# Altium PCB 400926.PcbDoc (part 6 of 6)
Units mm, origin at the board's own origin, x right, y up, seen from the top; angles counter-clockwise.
Board outline 148.5 x 63.5 mm, 4 copper layers (Top Layer, Mid-Layer 1, Mid-Layer 2, Bottom Layer), stack 1.514 mm thick; 311 components, 281 nets, 1495 pads, 2232 vias.
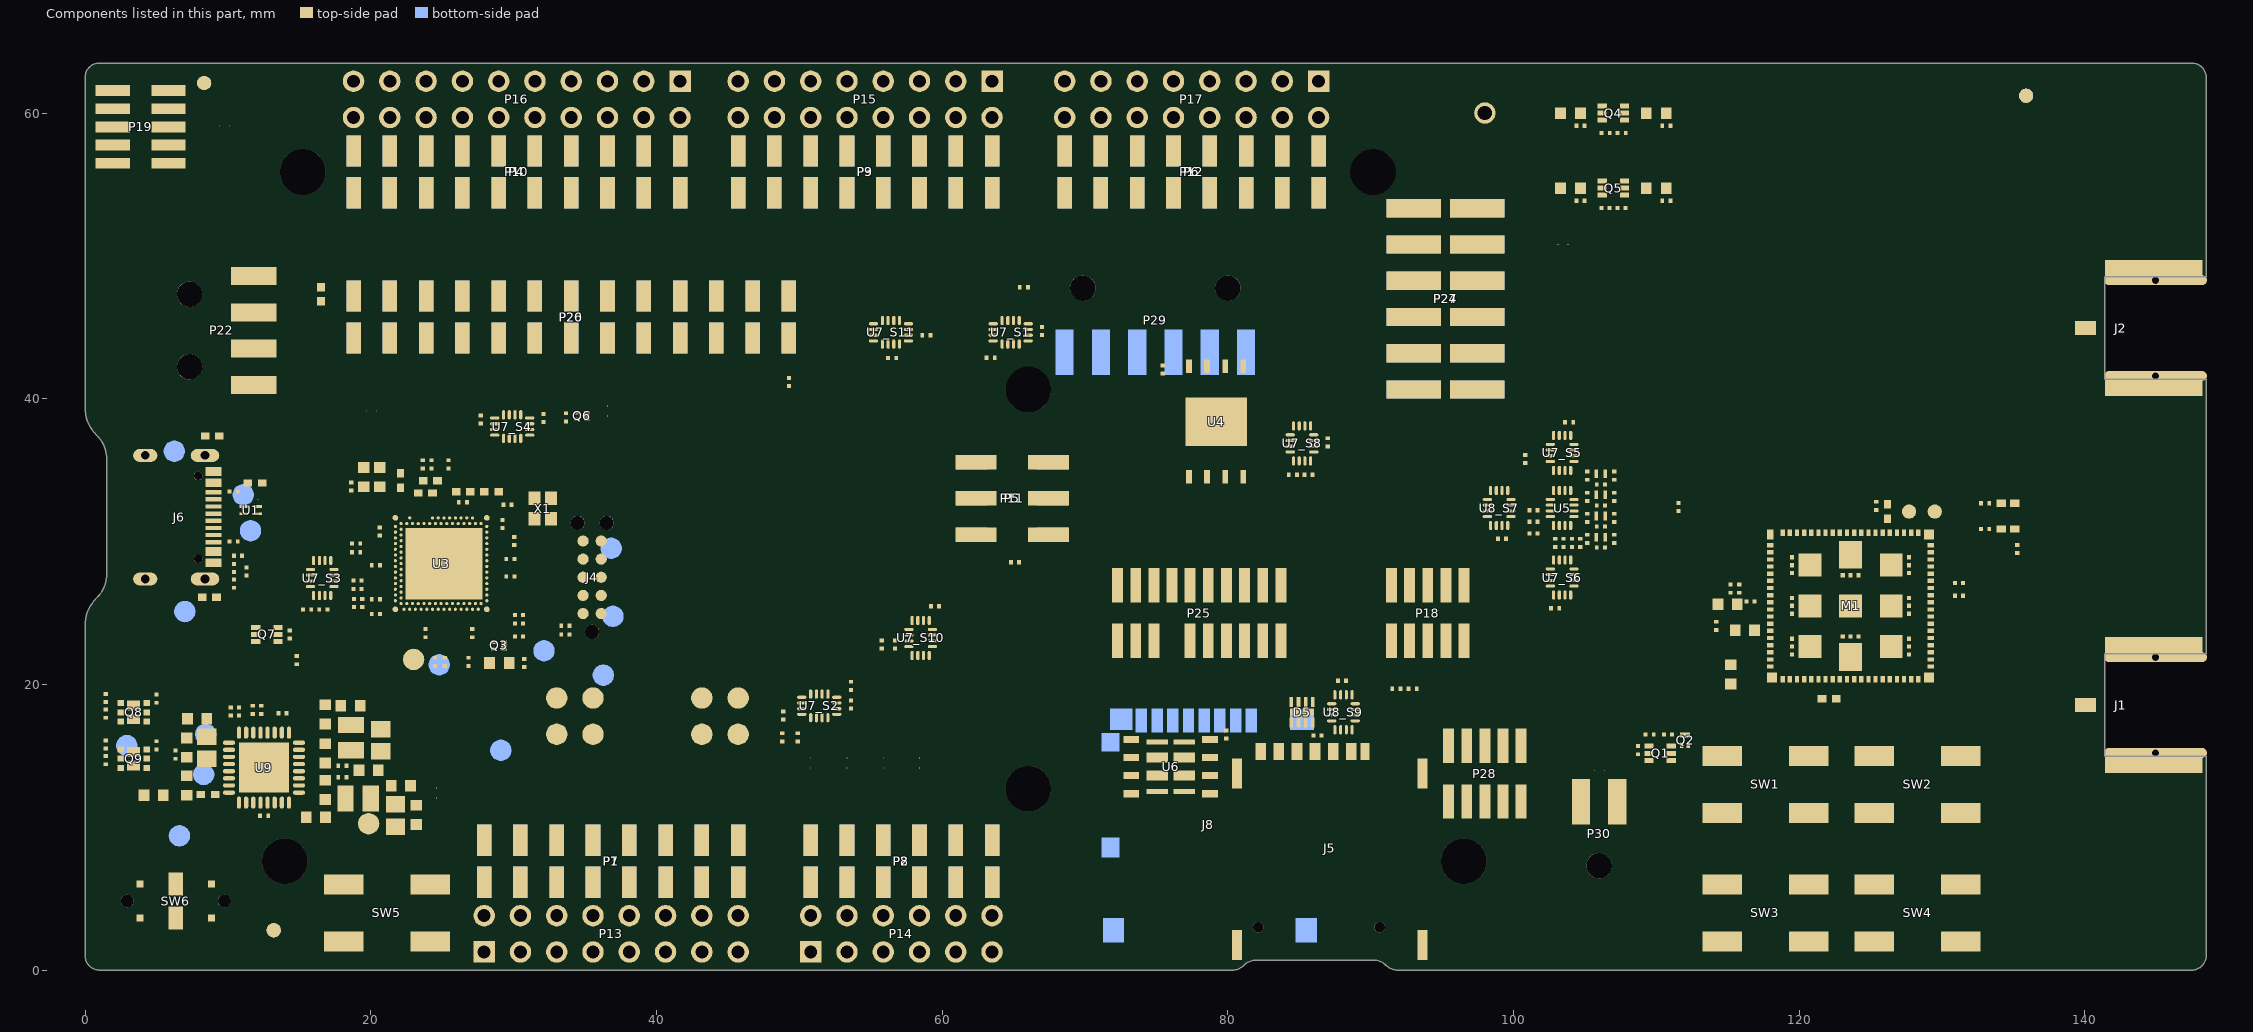
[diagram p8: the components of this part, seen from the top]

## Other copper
Top Layer:
  region net VIN:5V: 39.626,46.224 38.606,46.224 38.606,45.224 39.626,45.224
  region net VDD_nRF: 42.166,46.224 41.146,46.224 41.146,45.224 42.166,45.224
  region net LTE_RF1: 125.7,20.149 125.527,19.976 ccw(c125.954,19.549) 125.35,19.549 126.35,19.549 ccw(c125.746,19.549) 126.173,19.976 126,20.149 126,20.599 125.7,20.599
  region net GPS_RF1: 129.45,21.099 129.623,20.926 ccw(c130.05,21.352) 130.05,20.749 130.05,21.749 ccw(c130.05,21.145) 129.623,21.572 129.45,21.399 129,21.399 129,21.099
  region net VDD_1V8: 14.7,12.574 14.7,11.249 ccw(c16.45,11.249) 16.45,9.499 20.025,9.499 ccw(c20.025,10.074) 20.6,10.074 20.6,12.906 19.432,12.906 19.432,11.031 cw(c19.1,11.031) 19.1,10.699 ccw(c19.1,10.499) 18.9,10.499 18.9,10.299 cw(c18.725,10.299) 18.725,10.124 16.3,10.124 cw(c16.3,10.599) 15.825,10.599 15.825,11.604 15.25,12.084 15.25,12.574
  region net NetC70_2: 21.506,10.571 21.506,10.573 23.622,10.573 ccw(c23.622,11.07) 24.119,11.07 cw(c24.147,11.07) 24.147,11.098 25.011,11.098 cw(c25.011,11.022) 25.087,11.022 25.087,9.686 cw(c24.9,9.686) 24.9,9.499 21.074,9.499 cw(c21.074,9.521) 21.052,9.521 21.052,10.571
  region net VDD_1V8: 19.432,12.906 20.662,12.906 ccw(c20.662,13.296) 21.052,13.296 21.802,13.296 21.802,12.496 ccw(c22.177,12.496) 22.177,12.121 22.402,12.121 22.402,11.071 19.432,11.071
  region net NetC59_2: 16.427,18.958 cw(c16.465,18.958) 16.465,18.996 18.402,18.996 18.402,18.196 ccw(c18.874,18.196) 18.874,17.724 21.05,17.724 cw(c21.05,17.399) 21.375,17.399 21.375,16.349 20.025,16.349 ccw(c19.78,16.349) 19.78,16.594 17.715,16.594 17.715,17.724 ccw(c17.231,17.724) 17.231,18.208 16.427,18.208
  region net VSYS: 7.852,15.821 7.852,16.871 ccw(c7.852,17.171) 8.152,17.171 8.152,19.399 8.902,19.399 8.902,17.171 ccw(c9.202,17.171) 9.202,16.871 9.202,15.821
  region net VSYS: 14.975,14.074 14.975,13.774 15.405,13.774 cw(c15.405,13.264) 15.747,13.642 cw(c11.993,9.491) 16.416,12.921 17.227,12.921 17.227,14.871 16.416,14.871 cw(c13.851,16.714) 15.837,14.258 cw(c15.317,14.901) 15.317,14.074
  region net NetC57_2: 6.725,14.524 6.725,15.274 9.2,15.274 ccw(c10.306,15.577) 9.75,14.574 10.15,14.574 10.15,14.274 6.975,14.274 cw(c6.975,14.524)
  region net VDD_5V: 6.7,13.974 6.7,13.249 ccw(c6.725,13.249) 6.725,13.224 8.165,13.224 ccw(c8.165,13.43) 8.31,13.284 8.697,13.671 cw(c8.946,13.422) 8.946,13.774 10.325,13.774 10.325,14.074 6.8,14.074 ccw(c6.8,13.974)
  region net VIN:5V: 2.27,15.239 2.27,16.144 cw(c2.65,16.144) 2.65,16.524 4.15,16.524 cw(c4.15,16.199) 4.475,16.199 cw(c4.15,16.199) 4.15,15.874 2.935,15.874 ccw(c2.935,15.659) 2.72,15.659 2.72,15.239
  region net VDD_nRF: 111.048,31.744 111.05,31.746 111.05,31.889 cw(c111.256,31.889) 111.11,32.034 111.307,32.231 cw(c111.41,32.128) 111.41,32.274 111.679,32.274 cw(c111.679,32.103) 111.8,32.224 112.007,32.017 cw(c111.906,31.915) 112.049,31.915 112.049,31.741
  region net VDD_5V: 43.446,42.58 44.946,42.58 cw(c44.946,42.255) 45.271,42.255 cw(c44.946,42.255) 44.946,41.93 43.446,41.93 cw(c43.446,42.255) 43.121,42.255 cw(c43.446,42.255)
  region net VDD: 71.375,20.849 70.5,20.849 ccw(c70.5,20.349) 70,20.349 ccw(c70.5,20.349) 70.5,19.849 71.375,19.849
  region net VDD: 71.125,20.849 72,20.849 cw(c72,20.349) 72.5,20.349 cw(c72,20.349) 72,19.849 71.125,19.849
  region net VDD: 22.558,39.484 23.177,38.865 ccw(c23.53,39.219) 23.884,38.865 ccw(c23.53,39.219) 23.884,39.572 23.265,40.191
  region net VDD: 22.735,39.307 22.116,39.926 cw(c22.47,40.279) 22.116,40.633 cw(c22.47,40.279) 22.823,40.633 23.442,40.014
  region net VDD_5V: 16.144,38.659 16.144,36.748 cw(c15.819,36.75) 15.494,36.75 15.494,38.659 cw(c15.819,38.659) 15.819,38.984 cw(c15.819,38.659)
  pour cut-out: 124.477,20.799 125.125,20.799 125.125,20.174 124.477,20.174
  pour cut-out: 127.223,20.799 126.575,20.799 126.575,20.174 127.223,20.174
  pour cut-out: 135.522,29.555 135.608,29.519 135.774,29.409 135.807,29.376 135.84,29.343 135.95,29.177 135.986,29.091 136.025,28.896 136.025,28.872 136.029,28.849 136.029,22.851 136.03,22.849 136.027,22.837 136.029,22.826 135.988,22.414 135.981,22.391 135.979,22.368 135.859,21.972 135.848,21.951 135.841,21.929 135.646,21.564 135.631,21.545 135.62,21.525 135.357,21.205 135.339,21.19 135.324,21.172 135.004,20.909 134.983,20.898 134.965,20.883 134.6,20.688 134.578,20.681 134.557,20.67 134.161,20.55 134.138,20.548 134.115,20.541 133.703,20.5 133.692,20.502 133.68,20.499 133.678,20.5 130.05,20.5 130.027,20.504 130.003,20.504 129.947,20.516 129.938,20.516 129.929,20.519 129.925,20.52 129.915,20.52 129.856,20.531 129.847,20.535 129.842,20.536 129.834,20.537 129.825,20.54 129.808,20.543 129.792,20.55 129.777,20.554 129.766,20.56 129.755,20.562 129.7,20.585 129.69,20.592 129.679,20.595 129.626,20.623 129.617,20.631 129.606,20.635 129.557,20.668 129.549,20.676 129.538,20.682 129.492,20.72 129.485,20.729 129.475,20.735 129.454,20.756 129.351,20.859 129,20.859 128.908,20.878 128.831,20.93 128.779,21.007 128.76,21.099 128.76,21.399 128.779,21.491 128.831,21.568 128.908,21.62 129,21.638 129.351,21.638 129.454,21.742 129.475,21.763 129.485,21.769 129.492,21.778 129.538,21.816 129.549,21.822 129.557,21.83 129.606,21.863 129.617,21.867 129.626,21.875 129.679,21.903 129.69,21.906 129.7,21.913 129.755,21.936 129.766,21.938 129.777,21.944 129.792,21.948 129.808,21.955 129.826,21.958 129.834,21.961 129.842,21.962 129.847,21.963 129.856,21.967 129.915,21.978 129.925,21.978 129.93,21.979 129.938,21.982 129.946,21.982 130.003,21.994 130.027,21.994 130.05,21.998 133.68,21.998 133.693,21.996 133.901,22.023 134.108,22.108 134.285,22.244 134.421,22.421 134.506,22.628 134.533,22.836 134.531,22.849 134.531,28.849 134.535,28.872 134.535,28.896 134.574,29.091 134.61,29.177 134.72,29.343 134.753,29.376 134.786,29.409 134.952,29.519 135.038,29.555 135.233,29.594 135.327,29.594
  pour cut-out: 140.123,45.694 140.147,45.694 140.208,45.681 140.8,45.681 140.892,45.663 140.969,45.611 141.021,45.534 141.04,45.442 141.04,44.442 141.021,44.35 140.969,44.273 140.892,44.221 140.8,44.202 140.114,44.202 140.1,44.2 137.82,44.2 137.801,44.204 137.47,44.171 137.133,44.069 136.822,43.903 136.55,43.679 136.326,43.407 136.16,43.096 136.058,42.759 136.025,42.428 136.026,42.428 136.029,42.409 136.029,30.879 136.029,30.089 136.025,30.066 136.025,30.042 135.986,29.847 135.95,29.761 135.84,29.595 135.807,29.562 135.774,29.529 135.608,29.419 135.522,29.383 135.327,29.344 135.233,29.344 135.038,29.383 134.952,29.419 134.786,29.529 134.753,29.562 134.72,29.595 134.61,29.761 134.574,29.847 134.535,30.042 134.535,30.066 134.531,30.089 134.531,30.879 134.531,42.409 134.533,42.42 134.532,42.428 134.569,42.905 134.574,42.923 134.575,42.942 134.687,43.407 134.695,43.424 134.699,43.443 134.882,43.885 134.892,43.901 134.899,43.919 135.149,44.327 135.162,44.34 135.171,44.357 135.482,44.721 135.496,44.733 135.508,44.747 135.872,45.058 135.889,45.067 135.902,45.08 136.31,45.33 136.328,45.337 136.344,45.347 136.786,45.53 136.805,45.534 136.822,45.542 137.287,45.654 137.306,45.654 137.324,45.66 137.801,45.697 137.809,45.696 137.82,45.698 140.1,45.698
  pour cut-out: 126.092,20.82 126.169,20.768 126.221,20.691 126.24,20.599 126.24,20.248 126.343,20.145 126.364,20.124 126.37,20.114 126.379,20.107 126.417,20.061 126.423,20.05 126.431,20.042 126.464,19.993 126.468,19.982 126.476,19.973 126.504,19.92 126.507,19.909 126.514,19.899 126.537,19.844 126.538,19.837 126.544,19.824 126.545,19.822 126.545,19.82 126.556,19.794 126.561,19.767 126.562,19.765 126.562,19.764 126.565,19.749 126.568,19.743 126.579,19.684 126.579,19.678 126.582,19.663 126.583,19.661 126.583,19.66 126.595,19.599 126.595,19.58 126.608,19.513 126.636,19.471 126.756,19.379 126.906,19.317 127.058,19.297 127.066,19.298 140.1,19.298 140.123,19.294 140.147,19.294 140.208,19.281 140.8,19.281 140.892,19.263 140.969,19.211 141.021,19.134 141.04,19.042 141.04,18.042 141.021,17.95 140.969,17.873 140.892,17.821 140.8,17.802 140.114,17.802 140.1,17.8 127.066,17.8 127.051,17.802 127.042,17.802 126.676,17.838 126.654,17.844 126.63,17.847 126.279,17.953 126.258,17.965 126.235,17.971 125.911,18.145 125.893,18.16 125.872,18.171 125.588,18.404 125.586,18.406 125.569,18.418 125.56,18.431 125.548,18.441 125.331,18.724 125.317,18.752 125.3,18.778 125.164,19.107 125.157,19.138 125.147,19.168 125.101,19.521 125.102,19.537 125.099,19.552 125.105,19.583 125.105,19.589 125.105,19.599 125.106,19.604 125.107,19.614 125.109,19.619 125.117,19.659 125.117,19.661 125.118,19.663 125.121,19.678 125.121,19.684 125.132,19.743 125.135,19.749 125.138,19.764 125.138,19.765 125.139,19.767 125.144,19.794 125.155,19.82 125.155,19.822 125.156,19.824 125.162,19.837 125.163,19.844 125.186,19.899 125.193,19.909 125.196,19.92 125.224,19.973 125.232,19.982 125.236,19.993 125.269,20.042 125.277,20.05 125.283,20.061 125.321,20.107 125.33,20.114 125.336,20.124 125.357,20.145 125.46,20.248 125.46,20.599 125.479,20.691 125.531,20.768 125.608,20.82 125.7,20.839 126,20.839
  pour cut-out: 139.85,19.298 141.2,19.298 141.2,17.8 139.85,17.8
  pour cut-out: 134.531,28.849 134.531,30.089 136.029,30.089 136.029,28.849
  pour cut-out: 139.85,45.698 141.2,45.698 141.2,44.2 139.85,44.2
  pour cut-out: 17.859,10.299 17.859,10.999 17.232,10.999 17.232,10.299
  pour cut-out: 19.552,13.193 19.552,13.346 18.162,13.346 18.162,13.193
  pour cut-out: 19.552,14.446 19.552,14.599 18.162,14.599 18.162,14.446
  pour cut-out: 19.814,13.346 19.814,14.446 19.552,14.446 19.552,13.346
  pour cut-out: 18.162,13.346 18.162,14.446 17.9,14.446 17.9,13.346
  pour cut-out: 16.175,16.274 15.425,15.524 15.59,15.359 16.34,16.109
  pour cut-out: 16.241,15.498 15.491,14.748 15.592,14.647 16.342,15.397
  region net GND: 18.162,14.446 19.552,14.446 19.552,13.346 18.161,13.346
  region net GND: 14.9,14.799 15.54,14.799 16.24,15.499 17.227,15.499 17.227,17.315 16.423,17.315 16.423,16.221 15.305,15.066 14.9,15.066
  region net VDD_3V0: 20.152,13.596 20.152,14.396 20.023,14.821 20.023,15.849 21.379,15.849 21.379,13.596
  region net VDD_5V: 4.55,11.149 4.55,14.349 4.05,14.349 4.05,13.749 3.65,13.749 3.65,11.149
  pour cut-out: 16.405,11.793 15.425,12.774 15.324,12.673 16.305,11.693
  pour cut-out: 16.348,12.425 15.599,13.175 15.498,13.074 16.248,12.324
  pour cut-out: 19.432,10.999 19.432,13.028 18.792,13.028 18.792,10.999
  pour cut-out: 16.2,17.608 16.2,15.421 16.427,15.421 16.427,17.608
  region net GND: 17.227,10.299 16.425,10.299 16.425,11.774 15.425,12.774 15.1,12.774 15.1,13.074 15.498,13.074 16.248,12.324 17.227,12.324
  pour cut-out: 30.6,21.999 30.1,21.999 30.1,20.999 30.6,20.999
  pour cut-out: 29.2,21.999 28.7,21.999 28.7,20.999 29.2,20.999
  region net 5V: 38.61,3.81 38.61,10.199 37.59,10.199 37.59,3.81
  region net FB2:VBUS: 10.3,26.899 11,26.899 11,27.699 11.6,27.699 11.6,26.699 11.2,26.299 10.3,26.299
  region net VDD_5V: 44.706,47.074 44.706,42.955 45.222,42.439 43.17,42.439 43.686,42.955 43.686,47.074
  pour cut-out: 30.792,34.198 30.792,30.465 33.104,30.465 33.104,34.198
Mid-Layer 1:
  pour cut-out: 133.28,31.204 134.395,31.204 cw(c134.395,31.044) 134.555,31.044 134.555,30.729 cw(c134.38,30.729) 134.38,30.554 133.295,30.554 cw(c133.295,30.746) 133.102,30.746 133.102,31.026 cw(c133.28,31.026)
  pour cut-out: 13.225,22.349 13.775,22.349 cw(c13.775,21.999) 14.125,21.999 14.125,21.424 cw(c13.775,21.424) 13.775,21.074 13.225,21.074 cw(c13.225,21.424) 12.875,21.424 12.875,21.999 cw(c13.225,21.999)
  pour cut-out: 3.825,11.549 4.375,11.549 cw(c4.375,11.199) 4.725,11.199 4.725,10.624 cw(c4.375,10.624) 4.375,10.274 3.825,10.274 cw(c3.825,10.624) 3.475,10.624 3.475,11.199 cw(c3.825,11.199)
  pour cut-out: 84.625,29.524 84.625,28.974 cw(c84.275,28.974) 84.275,28.624 83.7,28.624 cw(c83.7,28.974) 83.35,28.974 83.35,29.524 cw(c83.7,29.524) 83.7,29.874 84.275,29.874 cw(c84.275,29.524)
  pour cut-out: 72.125,15.524 72.125,14.974 cw(c71.775,14.974) 71.775,14.624 71.2,14.624 cw(c71.2,14.974) 70.85,14.974 70.85,15.524 cw(c71.2,15.524) 71.2,15.874 71.775,15.874 cw(c71.775,15.524)
  pour cut-out: 72.125,13.524 72.125,12.974 cw(c71.775,12.974) 71.775,12.624 71.2,12.624 cw(c71.2,12.974) 70.85,12.974 70.85,13.524 cw(c71.2,13.524) 71.2,13.874 71.775,13.874 cw(c71.775,13.524)
  pour cut-out: 106.625,14.249 106.625,13.699 cw(c106.275,13.699) 106.275,13.349 105.7,13.349 cw(c105.7,13.699) 105.35,13.699 105.35,14.249 cw(c105.7,14.249) 105.7,14.599 106.275,14.599 cw(c106.275,14.249)
  pour cut-out: 56.275,29.855 55.725,29.855 cw(c55.725,30.205) 55.375,30.205 55.375,30.78 cw(c55.725,30.78) 55.725,31.13 56.275,31.13 cw(c56.275,30.78) 56.625,30.78 56.625,30.205 cw(c56.275,30.205)
  pour cut-out: 56.625,32.255 56.625,31.705 cw(c56.275,31.705) 56.275,31.355 55.7,31.355 cw(c55.7,31.705) 55.35,31.705 55.35,32.255 cw(c55.7,32.255) 55.7,32.605 56.275,32.605 cw(c56.275,32.255)
  pour cut-out: 56.625,29.255 56.625,28.705 cw(c56.275,28.705) 56.275,28.355 55.7,28.355 cw(c55.7,28.705) 55.35,28.705 55.35,29.255 cw(c55.7,29.255) 55.7,29.605 56.275,29.605 cw(c56.275,29.255)
  pour cut-out: 67.625,26.524 67.625,25.974 cw(c67.275,25.974) 67.275,25.624 66.7,25.624 cw(c66.7,25.974) 66.35,25.974 66.35,26.524 cw(c66.7,26.524) 66.7,26.874 67.275,26.874 cw(c67.275,26.524)
  pour cut-out: 67.625,28.024 67.625,27.474 cw(c67.275,27.474) 67.275,27.124 66.7,27.124 cw(c66.7,27.474) 66.35,27.474 66.35,28.024 cw(c66.7,28.024) 66.7,28.374 67.275,28.374 cw(c67.275,28.024)
  pour cut-out: 58.775,25.624 58.225,25.624 cw(c58.225,25.974) 57.875,25.974 57.875,26.549 cw(c58.225,26.549) 58.225,26.899 58.775,26.899 cw(c58.775,26.549) 59.125,26.549 59.125,25.974 cw(c58.775,25.974)
  pour cut-out: 57.275,25.624 56.725,25.624 cw(c56.725,25.974) 56.375,25.974 56.375,26.549 cw(c56.725,26.549) 56.725,26.899 57.275,26.899 cw(c57.275,26.549) 57.625,26.549 57.625,25.974 cw(c57.275,25.974)
  pour cut-out: 56.275,23.624 55.725,23.624 cw(c55.725,23.974) 55.375,23.974 55.375,24.549 cw(c55.725,24.549) 55.725,24.899 56.275,24.899 cw(c56.275,24.549) 56.625,24.549 56.625,23.974 cw(c56.275,23.974)
  pour cut-out: 58.725,20.874 59.275,20.874 cw(c59.275,20.524) 59.625,20.524 59.625,19.949 cw(c59.275,19.949) 59.275,19.599 58.725,19.599 cw(c58.725,19.949) 58.375,19.949 58.375,20.524 cw(c58.725,20.524)
  pour cut-out: 57.775,19.624 57.225,19.624 cw(c57.225,19.974) 56.875,19.974 56.875,20.549 cw(c57.225,20.549) 57.225,20.899 57.775,20.899 cw(c57.775,20.549) 58.125,20.549 58.125,19.974 cw(c57.775,19.974)
  pour cut-out: 58.145,15.124 58.695,15.124 cw(c58.695,14.774) 59.045,14.774 59.045,14.199 cw(c58.695,14.199) 58.695,13.849 58.145,13.849 cw(c58.145,14.199) 57.795,14.199 57.795,14.774 cw(c58.145,14.774)
  pour cut-out: 56.155,13.874 55.605,13.874 cw(c55.605,14.224) 55.255,14.224 55.255,14.799 cw(c55.605,14.799) 55.605,15.149 56.155,15.149 cw(c56.155,14.799) 56.505,14.799 56.505,14.224 cw(c56.155,14.224)
  pour cut-out: 53.065,15.124 53.615,15.124 cw(c53.615,14.774) 53.965,14.774 53.965,14.199 cw(c53.615,14.199) 53.615,13.849 53.065,13.849 cw(c53.065,14.199) 52.715,14.199 52.715,14.774 cw(c53.065,14.774)
  pour cut-out: 51.075,13.874 50.525,13.874 cw(c50.525,14.224) 50.175,14.224 50.175,14.799 cw(c50.525,14.799) 50.525,15.149 51.075,15.149 cw(c51.075,14.799) 51.425,14.799 51.425,14.224 cw(c51.075,14.224)
  pour cut-out: 24.325,11.824 24.875,11.824 cw(c24.875,11.474) 25.225,11.474 25.225,10.899 cw(c24.875,10.899) 24.875,10.549 24.325,10.549 cw(c24.325,10.899) 23.975,10.899 23.975,11.474 cw(c24.325,11.474)
  pour cut-out: 23.937,12.174 23.937,12.724 cw(c24.287,12.724) 24.287,13.074 24.862,13.074 cw(c24.862,12.724) 25.212,12.724 25.212,12.174 cw(c24.863,12.174) 24.862,11.824 24.287,11.824 cw(c24.287,12.174)
  pour cut-out: 26.8,11.474 26.8,10.924 cw(c26.45,10.924) 26.45,10.574 25.875,10.574 cw(c25.875,10.924) 25.525,10.924 25.525,11.474 cw(c25.875,11.474) 25.875,11.824 26.45,11.824 cw(c26.45,11.474)
  pour cut-out: 9.125,56.974 9.125,57.524 cw(c9.475,57.524) 9.475,57.874 10.05,57.874 cw(c10.05,57.524) 10.4,57.524 10.4,56.974 cw(c10.05,56.974) 10.05,56.624 9.475,56.624 cw(c9.475,56.974)
  pour cut-out: 9.125,58.819 9.125,59.369 cw(c9.475,59.369) 9.475,59.719 10.05,59.719 cw(c10.05,59.369) 10.4,59.369 10.4,58.819 cw(c10.05,58.819) 10.05,58.469 9.475,58.469 cw(c9.475,58.819)
  pour cut-out: 15.515,46.693 14.965,46.693 cw(c14.965,47.043) 14.615,47.043 14.615,47.618 cw(c14.965,47.618) 14.965,47.968 15.515,47.968 cw(c15.515,47.618) 15.865,47.618 15.865,47.043 cw(c15.515,47.043)
  pour cut-out: 19.791,39.772 20.341,39.772 cw(c20.341,39.422) 20.691,39.422 20.691,38.847 cw(c20.341,38.847) 20.341,38.497 19.791,38.497 cw(c19.791,38.847) 19.441,38.847 19.441,39.422 cw(c19.791,39.422)
  pour cut-out: 36.3,39.786 36.85,39.786 cw(c36.85,39.436) 37.2,39.436 37.2,38.861 cw(c36.85,38.861) 36.85,38.511 36.3,38.511 cw(c36.3,38.861) 35.95,38.861 35.95,39.436 cw(c36.3,39.436)
  pour cut-out: 73.935,41.579 73.385,41.579 cw(c73.385,41.929) 73.035,41.929 73.035,42.504 cw(c73.385,42.504) 73.385,42.854 73.935,42.854 cw(c73.935,42.504) 74.285,42.504 74.285,41.929 cw(c73.935,41.929)
  pour cut-out: 73.385,49.624 73.935,49.624 cw(c73.935,49.274) 74.285,49.274 74.285,48.699 cw(c73.935,48.699) 73.935,48.349 73.385,48.349 cw(c73.385,48.699) 73.035,48.699 73.035,49.274 cw(c73.385,49.274)
  pour cut-out: 70.845,49.624 71.395,49.624 cw(c71.395,49.274) 71.745,49.274 71.745,48.699 cw(c71.395,48.699) 71.395,48.349 70.845,48.349 cw(c70.845,48.699) 70.495,48.699 70.495,49.274 cw(c70.845,49.274)
  pour cut-out: 68.305,49.624 68.855,49.624 cw(c68.855,49.274) 69.205,49.274 69.205,48.699 cw(c68.855,48.699) 68.855,48.349 68.305,48.349 cw(c68.305,48.699) 67.955,48.699 67.955,49.274 cw(c68.305,49.274)
  pour cut-out: 104.097,51.075 104.097,50.525 cw(c103.747,50.525) 103.747,50.175 103.172,50.175 cw(c103.172,50.525) 102.822,50.525 102.822,51.075 cw(c103.172,51.075) 103.172,51.425 103.747,51.425 cw(c103.748,51.075)
  pour cut-out: 135.505,29.406 135.505,28.981 135.055,28.981 135.055,29.406
  pour cut-out: 135.505,29.976 135.505,29.551 135.055,29.551 135.055,29.976
  pour cut-out: 133.102,33.004 134.555,33.004 134.555,32.354 133.102,32.354
  pour cut-out: 134.705,31.204 135.505,31.204 135.505,30.554 134.705,30.554
  pour cut-out: 134.705,33.004 135.505,33.004 135.505,32.354 134.705,32.354
  pour cut-out: 139.85,19.298 141.2,19.298 141.2,17.8 139.85,17.8
  pour cut-out: 135.522,29.555 135.608,29.519 135.774,29.409 135.807,29.376 135.84,29.343 135.95,29.177 135.986,29.091 136.025,28.896 136.025,28.872 136.029,28.849 136.029,22.851 136.03,22.849 136.027,22.837 136.029,22.826 135.988,22.414 135.981,22.391 135.979,22.368 135.859,21.972 135.848,21.951 135.841,21.929 135.646,21.564 135.631,21.545 135.62,21.525 135.357,21.205 135.339,21.19 135.324,21.172 135.004,20.909 134.983,20.898 134.965,20.883 134.6,20.688 134.578,20.681 134.557,20.67 134.161,20.55 134.138,20.548 134.115,20.541 133.703,20.5 133.692,20.502 133.68,20.499 133.678,20.5 130.05,20.5 130.027,20.504 130.003,20.504 129.947,20.516 129.938,20.516 129.929,20.519 129.925,20.52 129.915,20.52 129.856,20.531 129.847,20.535 129.842,20.536 129.834,20.537 129.825,20.54 129.808,20.543 129.792,20.55 129.777,20.554 129.766,20.56 129.755,20.562 129.7,20.585 129.69,20.592 129.679,20.595 129.626,20.623 129.617,20.631 129.606,20.635 129.557,20.668 129.549,20.676 129.538,20.682 129.492,20.72 129.485,20.729 129.475,20.735 129.454,20.756 129.351,20.859 129,20.859 128.908,20.878 128.831,20.93 128.779,21.007 128.76,21.099 128.76,21.399 128.779,21.491 128.831,21.568 128.908,21.62 129,21.638 129.351,21.638 129.454,21.742 129.475,21.763 129.485,21.769 129.492,21.778 129.538,21.816 129.549,21.822 129.557,21.83 129.606,21.863 129.617,21.867 129.626,21.875 129.679,21.903 129.69,21.906 129.7,21.913 129.755,21.936 129.766,21.938 129.777,21.944 129.792,21.948 129.808,21.955 129.826,21.958 129.834,21.961 129.842,21.962 129.847,21.963 129.856,21.967 129.915,21.978 129.925,21.978 129.93,21.979 129.938,21.982 129.946,21.982 130.003,21.994 130.027,21.994 130.05,21.998 133.68,21.998 133.693,21.996 133.901,22.023 134.108,22.108 134.285,22.244 134.421,22.421 134.506,22.628 134.533,22.836 134.531,22.849 134.531,28.849 134.535,28.872 134.535,28.896 134.574,29.091 134.61,29.177 134.72,29.343 134.753,29.376 134.786,29.409 134.952,29.519 135.038,29.555 135.233,29.594 135.327,29.594
  pour cut-out: 134.531,28.849 134.531,30.089 136.029,30.089 136.029,28.849
  pour cut-out: 139.85,45.698 141.2,45.698 141.2,44.2 139.85,44.2
  pour cut-out: 126.092,20.82 126.169,20.768 126.221,20.691 126.24,20.599 126.24,20.248 126.343,20.145 126.364,20.124 126.37,20.114 126.379,20.107 126.417,20.061 126.423,20.05 126.431,20.042 126.464,19.993 126.468,19.982 126.476,19.973 126.504,19.92 126.507,19.909 126.514,19.899 126.537,19.844 126.538,19.837 126.544,19.824 126.545,19.822 126.545,19.82 126.556,19.794 126.561,19.767 126.562,19.765 126.562,19.764 126.565,19.749 126.568,19.743 126.579,19.684 126.579,19.678 126.582,19.663 126.583,19.661 126.583,19.66 126.595,19.599 126.595,19.58 126.608,19.513 126.636,19.471 126.756,19.379 126.906,19.317 127.058,19.297 127.066,19.298 139.85,19.298 139.873,19.294 139.897,19.294 139.923,19.288 140.6,19.288 140.692,19.27 140.769,19.218 140.821,19.141 140.84,19.049 140.84,18.049 140.821,17.957 140.769,17.88 140.692,17.828 140.6,17.809 139.923,17.809 139.897,17.804 139.873,17.804 139.85,17.8 127.066,17.8 127.051,17.802 127.042,17.802 126.676,17.838 126.654,17.844 126.63,17.847 126.279,17.953 126.258,17.965 126.235,17.971 125.911,18.145 125.893,18.16 125.872,18.171 125.588,18.404 125.586,18.406 125.569,18.418 125.56,18.431 125.548,18.441 125.331,18.724 125.317,18.752 125.3,18.778 125.164,19.107 125.157,19.138 125.147,19.168 125.101,19.521 125.102,19.537 125.099,19.552 125.105,19.583 125.105,19.589 125.105,19.599 125.106,19.604 125.107,19.614 125.109,19.619 125.117,19.659 125.117,19.661 125.118,19.663 125.121,19.678 125.121,19.684 125.132,19.743 125.135,19.749 125.138,19.764 125.138,19.765 125.139,19.767 125.144,19.794 125.155,19.82 125.155,19.822 125.156,19.824 125.162,19.837 125.163,19.844 125.186,19.899 125.193,19.909 125.196,19.92 125.224,19.973 125.232,19.982 125.236,19.993 125.269,20.042 125.277,20.05 125.283,20.061 125.321,20.107 125.33,20.114 125.336,20.124 125.357,20.145 125.46,20.248 125.46,20.599 125.479,20.691 125.531,20.768 125.608,20.82 125.7,20.839 126,20.839
  pour cut-out: 139.873,45.694 139.897,45.694 140.092,45.655 140.178,45.619 140.344,45.509 140.377,45.476 140.41,45.443 140.52,45.277 140.556,45.191 140.595,44.996 140.595,44.902 140.556,44.707 140.52,44.621 140.41,44.455 140.377,44.422 140.344,44.389 140.178,44.279 140.092,44.243 139.897,44.204 139.873,44.204 139.85,44.2 137.82,44.2 137.801,44.204 137.47,44.171 137.133,44.069 136.822,43.903 136.55,43.679 136.326,43.407 136.16,43.096 136.058,42.759 136.025,42.428 136.026,42.428 136.029,42.409 136.029,30.089 136.025,30.066 136.025,30.042 135.986,29.847 135.95,29.761 135.84,29.595 135.807,29.562 135.774,29.529 135.608,29.419 135.522,29.383 135.327,29.344 135.233,29.344 135.038,29.383 134.952,29.419 134.786,29.529 134.753,29.562 134.72,29.595 134.61,29.761 134.574,29.847 134.535,30.042 134.535,30.066 134.531,30.089 134.531,42.409 134.533,42.42 134.532,42.428 134.569,42.905 134.574,42.923 134.575,42.942 134.687,43.407 134.695,43.424 134.699,43.443 134.882,43.885 134.892,43.901 134.899,43.919 135.149,44.327 135.162,44.34 135.171,44.357 135.482,44.721 135.496,44.733 135.508,44.747 135.872,45.058 135.889,45.067 135.902,45.08 136.31,45.33 136.328,45.337 136.344,45.347 136.786,45.53 136.805,45.534 136.822,45.542 137.287,45.654 137.306,45.654 137.324,45.66 137.801,45.697 137.809,45.696 137.82,45.698 139.85,45.698
Mid-Layer 2:
  region net VDD_nRF: 111,32.199 112.1,32.199 cw(c112.1,31.999) 112.3,31.999 112.3,31.399 110.8,31.399 110.8,31.999 cw(c111,31.999)
  region net VDD_5V: 15.494,36.749 15.494,38.249 cw(c15.819,38.249) 15.819,38.574 cw(c15.819,38.249) 16.144,38.249 16.144,36.749 cw(c15.819,36.749) 15.819,36.424 cw(c15.819,36.749)
  region net VIN:5V: 38.791,44.22 38.791,45.72 cw(c39.116,45.72) 39.116,46.045 cw(c39.116,45.72) 39.441,45.72 39.441,44.22 cw(c39.116,44.22) 39.116,43.895 cw(c39.116,44.22)
  region net VDD_5V: 43.446,42.58 44.946,42.58 cw(c44.946,42.255) 45.271,42.255 cw(c44.946,42.255) 44.946,41.93 43.446,41.93 cw(c43.446,42.255) 43.121,42.255 cw(c43.446,42.255)
  region net VDD: 23.301,38.989 22.24,40.05 cw(c22.47,40.279) 22.24,40.509 cw(c22.47,40.279) 22.699,40.509 23.76,39.448 cw(c23.53,39.219) 23.76,38.989 cw(c23.53,39.219)
  region net VDD: 71.375,20.849 70.5,20.849 ccw(c70.5,20.349) 70,20.349 ccw(c70.5,20.349) 70.5,19.849 71.375,19.849
  region net VDD: 71.125,20.849 72,20.849 cw(c72,20.349) 72.5,20.349 cw(c72,20.349) 72,19.849 71.125,19.849
  region net 5V: 66.972,35.235 68.472,35.235 ccw(c68.472,35.56) 68.797,35.56 ccw(c68.472,35.56) 68.472,35.885 66.972,35.885 ccw(c66.972,35.56) 66.647,35.56 ccw(c66.972,35.56)
  region net VIN:5V: 14.719,36.749 14.719,38.249 cw(c15.044,38.249) 15.044,38.574 cw(c15.044,38.249) 15.369,38.249 15.369,36.749 cw(c15.044,36.749) 15.044,36.424 cw(c15.044,36.749)
  region net VDD: 22.411,38.438 22.723,38.751 cw(c23.068,38.405) 23.068,38.894 23.595,38.894 22.145,40.344 22.145,39.792 cw(c21.717,39.792) 22.019,39.49 21.689,39.16
Bottom Layer:
  rectangle net VIN:5V: 38.606,45.224 39.626,46.224
  rectangle net VDD_nRF: 41.146,45.224 42.166,46.224
  region net VDD_nRF: 112.1,31.299 111,31.299 cw(c111,31.499) 110.8,31.499 110.8,32.799 111.782,32.799 112.3,32.281 112.3,31.499 cw(c112.1,31.499)
  region net 5V: 55.425,20.499 55.425,21.999 cw(c55.75,21.999) 55.75,22.324 cw(c55.75,21.999) 56.075,21.999 56.075,20.499 cw(c55.75,20.499) 55.75,20.174 cw(c55.75,20.499)
  region net VDD_5V: 43.446,42.58 44.946,42.58 cw(c44.946,42.255) 45.271,42.255 cw(c44.946,42.255) 44.946,41.93 43.446,41.93 cw(c43.446,42.255) 43.121,42.255 cw(c43.446,42.255)
  region net VDD: 22.735,39.307 22.116,39.926 cw(c22.47,40.279) 22.116,40.633 cw(c22.47,40.279) 22.823,40.633 23.442,40.014
  region net VDD: 22.558,39.484 23.177,38.865 ccw(c23.53,39.219) 23.884,38.865 ccw(c23.53,39.219) 23.884,39.572 23.265,40.191
  region net VIN:5V: 14.719,36.749 14.719,38.249 cw(c15.044,38.249) 15.044,38.574 cw(c15.044,38.249) 15.369,38.249 15.369,36.749 cw(c15.044,36.749) 15.044,36.424 cw(c15.044,36.749)
  region net VDD_5V: 16.144,38.249 16.144,36.749 cw(c15.819,36.749) 15.819,36.424 cw(c15.819,36.749) 15.494,36.749 15.494,38.249 cw(c15.819,38.249) 15.819,38.574 cw(c15.819,38.249)
  region net VSYS: 16.947,13.637 16.947,17.249 9.011,17.249 9.011,19.088 ccw(c8.647,19.088) 8.647,19.452 8.528,19.452 ccw(c8.528,19.124) 8.2,19.124 8.2,15.924 15.5,15.924 15.5,13.637
  region net 5V: 37.59,3.81 37.59,9.299 38.61,9.299 38.61,3.81
  region net VDD_5V: 43.686,47.074 43.686,42.955 43.17,42.439 45.222,42.439 44.706,42.955 44.706,47.074

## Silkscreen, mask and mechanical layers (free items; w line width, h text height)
Top Overlay:
  circle w0.254: c88.113,54.366 r0.127
  circle w0.254: c65.278,54.356 r0.127
  circle w0.254: c43.434,54.356 r0.127
  circle w0.254: c26.162,9.144 r0.127
  circle w0.254: c49.022,9.144 r0.127
  region: 78.374,9.073 78.374,8.329 73.156,8.361 74.122,9.328 78.119,9.328
  region: 78.296,3.107 78.296,2.247 78.119,2.07 73.281,2.07 73.104,2.247 73.174,2.317 73.174,3.129 78.274,3.129
  lines w0.1: 9.3,19.499 5.9,19.499 5.9,9.699 18.1,9.699 ; 11.4,19.499 21.7,19.499 21.7,14.299 ; 23.9,9.699 23.9,14.299 21.7,14.299 ; 21.7,14.299 21.7,14.299 ; 18.1,32.799 19.7,32.799 19.7,22.799 27.9,22.799 27.9,24.599 29.7,24.599 29.7,26.999 30.7,26.999 30.7,30.399 33.3,30.399 33.3,34.799 22.7,34.799 22.7,35.899 18.1,35.899 18.1,32.799
  lines w0.15: 37.084,17.779 41.656,17.779 ; 39.37,15.493 39.37,20.065 ; 37.084,15.493 37.084,20.065 41.656,20.065 41.656,15.493 37.084,15.493
  lines w0.25: 73.104,8.236 73.104,2.247 ccw(c73.281,2.247) 73.281,2.07 78.119,2.07 ccw(c78.119,2.247) 78.296,2.247 78.296,9.151 ccw(c78.119,9.151) 78.119,9.328 74.195,9.328 ; 73.155,8.361 74.07,9.276
  lines w0.254: 12.38,60.96 92.837,60.96 ; 14.224,62.23 17.018,62.23 ; 16.764,62.23 16.256,62.484 16.256,61.976 17.018,62.23 ; 26.67,2.54 67.996,2.54 ; 65.481,1.231 65.989,0.977 65.989,1.485 65.227,1.231 ; 68.021,1.231 65.227,1.231 ; 88.341,62.191 88.849,61.937 88.849,62.445 88.087,62.191 ; 90.881,62.191 88.087,62.191 ; 17.018,62.23 16.256,61.722 16.256,62.738 17.018,62.23 ; 65.227,1.231 65.989,0.723 65.989,1.739 65.227,1.231 ; 88.087,62.191 88.849,62.699 88.849,61.683 88.087,62.191
  text "'.PCBnumber'" at 138.674,61.711 h2.03
  text "GND" at 10.662,61.694 h1.78
  text "GND" at 91.198,61.655 h1.78
  text "'.PCBrevision'" at 138.803,60.501 h1.52
  text "For evaluation only; / not FCC approved for resale." at 114.7,58.905 h1.52
  text "GND" at 96.383,57.563 h1.78
  text "DEBUG OUT" at 0.418,53.687 h1.8
  text "COEX1" at 99.601,52.948 h1.3
  text "COEX0" at 87.337,52.918 h1.3
  text "COEX2" at 87.421,50.483 h1.3
  text "P0.11" at 34.537,50.464 h1.7 r90
  text "P0.29" at 99.601,50.417 h1.3
  text "nRF CURRENT / MEASUREMENT" at 0.418,50.295 h1.8
  text "P0.21" at 86.861,50.188 h1.7 r90
  text "P0.31" at 19.297,50.167 h1.7 r90
  text "GND" at 26.928,50.11 h1.7 r90
  text "P0.12" at 31.997,50.095 h1.7 r90
  text "P0.01" at 61.461,50.075 h1.7 r90
  text "P0.13" at 29.457,50.065 h1.7 r90
  text "GPS" at 143.05,49.999 h1.8
  text "P0.10" at 37.077,49.985 h1.7 r90
  text "P0.27" at 71.621,49.855 h1.7 r90
  text "P0.22" at 84.321,49.819 h1.7 r90
  text "P0.25" at 76.701,49.773 h1.7 r90
  text "P0.23" at 81.781,49.789 h1.7 r90
  text "P0.28" at 69.081,49.755 h1.7 r90
  text "P0.26" at 74.161,49.746 h1.7 r90
  text "P0.07" at 46.221,49.742 h1.7 r90
  text "P0.24" at 79.241,49.74 h1.7 r90
  text "P0.20" at 24.377,49.709 h1.7 r90
  text "P0.02" at 58.921,49.706 h1.7 r90
  text "P0.30" at 21.837,49.688 h1.7 r90
  text "P0.03" at 56.381,49.676 h1.7 r90
  text "P0.09" at 39.617,49.652 h1.7 r90
  text "P0.08" at 42.157,49.642 h1.7 r90
  text "P0.05" at 51.301,49.66 h1.7 r90
  text "P0.06" at 48.761,49.633 h1.7 r90
  text "P0.04" at 53.841,49.627 h1.7 r90
  text "P0.00" at 64.001,49.596 h1.7 r90
  text "VDD_nRF" at 0.6,49.228 h1.4
  text "SDATA" at 87.421,47.943 h1.3
  text "SCLK" at 99.601,47.868 h1.3
  text "VDD_5V" at 0.6,46.688 h1.4
  text "VIO" at 89.07,45.412 h1.27
  text "GND" at 99.601,45.328 h1.3
  text "NC" at 0.6,44.148 h1.4
  text "MAGPIO0" at 85.869,42.863 h1.3
  text "MAGPIO1" at 99.601,42.788 h1.3
  text "ID" at 49.667,41.988 h1.3 r90
  text "GND" at 0.6,41.608 h1.4
  text "SEL" at 36.968,41.193 h1.3 r90
  text "VIO / REF" at 47.721,40.959 h1.3 r90
  text "VTG" at 24.268,40.742 h1.3 r90
  text "VDD" at 21.727,40.668 h1.3 r90
  text "VDD / nRF" at 42.625,40.58 h1.3 r90
  text "VDD / 5V" at 45.165,40.58 h1.3 r90
  text "VIN / 5V" at 40.094,40.489 h1.3 r90
  text "VDD / GPIO" at 19.765,40.382 h1.3 r90
  text "SWD / IO" at 27.416,40.34 h1.3 r90
  text "SWD / CLK" at 29.956,40.34 h1.3 r90
  text "MAGPIO2" at 85.953,40.323 h1.3
  text "SWO" at 31.888,40.311 h1.3 r90
  text "GND" at 99.601,40.248 h1.3
  text "RESET" at 34.428,39.932 h1.3 r90
  text "'.Productname'" at 112.458,39.449 h3
  text "DEBUGGER" at 18.059,35.91 h1.8
  text "P0.12" at 57.761,35.102 h1.52
  text "5V" at 69.198,35.05 h1.52
  text "P0.11" at 69.197,32.588 h1.52
  text "P0.13" at 57.735,32.562 h1.52
  text "DETECT" at 69.197,30.09 h1.52
  text "RESET" at 57.107,30.019 h1.52
  text "TRACE" at 73.5,28.649 h1.8
  text "DEBUG IN" at 89.5,28.649 h1.8
  text "LTE" at 143.05,23.606 h1.8
  text "DEBUGGER" at 1.3,23.549 h1.8
  text "VCOM0" at 31.29,21.149 h1.8
  text "VCOM1" at 41.45,21.149 h1.8
  text "nPM1300" at 15.249,19.469 h1.8
  text "TxD" at 37.298,18.539 h1.27
  text "RxD" at 39.577,18.539 h1.27
  text "SIM / INTERFACE" at 93.685,17.349 h1.8
  text "MFF2 UICC" at 71.326,17.149 h1.8
  text "CTS" at 37.317,16.253 h1.27
  text "RTS" at 39.666,16.253 h1.27
  text "BUTTON 1" at 113.14,16.149 h1.8
  text "BUTTON 2" at 123.79,16.149 h1.8
  text "VDD" at 28.451,10.3 h1.7 r90
  text "VDD" at 30.991,10.3 h1.7 r90
  text "RESET" at 33.532,10.3 h1.7 r90
  text "VDD" at 36.071,10.3 h1.7 r90
  text "5V" at 38.601,10.3 h1.7 r90
  text "GND" at 41.152,10.3 h1.7 r90
  text "GND" at 43.692,10.3 h1.7 r90
  text "N.C." at 46.232,10.3 h1.7 r90
  text "P0.14" at 51.301,10.3 h1.7 r90
  text "P0.15" at 53.841,10.3 h1.7 r90
  text "P0.16" at 56.381,10.3 h1.7 r90
  text "P0.17" at 58.921,10.3 h1.7 r90
  text "P0.18" at 61.461,10.3 h1.7 r90
  text "P0.19" at 64.001,10.3 h1.7 r90
  text "POWER" at 1.85,7.149 h1.8
  text "RESET" at 16.636,7.149 h1.8
  text "BUTTON 3" at 113.14,7.149 h1.8
  text "BUTTON 4" at 123.79,7.149 h1.8
  text "NANO / SIM / CARD" at 78.2,2.949 h1.8 r90
  text "GND" at 68.338,0.695 h1.78
  text "OFF" at 0.75,0.649 h1.8
  text "ON" at 8.5,0.649 h1.8
  text "SIM CURRENT / MEASUREMENT" at 111.8,0.249 h1.8 r90
Bottom Overlay:
  drawing of 389 lines, arcs and shapes, not listed
  text "IOEXP_SCL" at 110.39,62.5 h1.91 r180
  text "P0.31" at 105.589,62.416 h1.91 r180
  text "P0.19" at 120.903,62.417 h1.91 r180
  text "Button 4" at 126.411,62.409 h1.91 r180
  text "nRF91" at 137.274,60.612 h2.03 r180
  text "IOEXP_SDA" at 110.212,59.96 h1.91 r180
  text "P0.30" at 105.321,59.876 h1.91 r180
  text "P0.18" at 120.899,59.877 h1.91 r180
  text "Button 3" at 126.439,59.869 h1.91 r180
  text "IOEXP_IRQ" at 110.418,57.42 h1.91 r180
  text "P0.19" at 105.518,57.336 h1.91 r180
  text "P0.09" at 120.687,57.336 h1.91 r180
  text "Button 2" at 126.457,57.336 h1.91 r180
  text "I2C" at 142.132,56.772 h1.78 r180
  text "GPIO" at 105.258,54.786 h2.03 r180
  text "Function" at 111.271,54.783 h2.03 r180
  text "P0.08" at 120.689,54.796 h1.91 r180
  text "Button 1" at 126.664,54.796 h1.91 r180
  text "BC" at 144.606,54.571 h1.78 r180
  text "COEX1" at 99.601,53.722 h1.27 r180
  text "COEX0" at 87.418,53.693 h1.27 r180
  text "P0.28" at 69.063,53.322 h1.78 r90
  text "P0.26" at 74.143,53.321 h1.78 r90
  text "P0.25" at 76.683,53.304 h1.78 r90
  text "P0.24" at 79.223,53.317 h1.78 r90
  text "P0.23" at 81.763,53.303 h1.78 r90
  text "P0.22" at 84.303,53.293 h1.78 r90
  text "P0.27" at 71.603,53.27 h1.78 r90
  text "P0.31" at 19.283,53.154 h1.65 r90
  text "P0.30" at 21.823,53.154 h1.65 r90
  text "P0.20" at 24.363,53.154 h1.65 r90
  text "GND" at 26.914,53.154 h1.65 r90
  text "P0.13" at 29.443,53.154 h1.65 r90
  text "P0.12" at 31.983,53.154 h1.65 r90
  text "P0.11" at 34.523,53.154 h1.65 r90
  text "P0.10" at 37.063,53.154 h1.65 r90
  text "P0.09" at 39.603,53.155 h1.65 r90
  text "P0.08" at 42.143,53.154 h1.65 r90
  text "P0.07" at 46.207,53.154 h1.65 r90
  text "P0.06" at 48.747,53.154 h1.65 r90
  text "P0.05" at 51.287,53.154 h1.65 r90
  text "P0.04 (D4)" at 53.74,53.158 h1.65 r90
  text "P0.03 (D3)" at 56.28,53.158 h1.65 r90
  text "P0.02 (D2)" at 58.82,53.157 h1.65 r90
  text "P0.01 (D1)" at 61.36,53.157 h1.65 r90
  text "P0.00 (ARDUINO D0)" at 63.9,53.165 h1.65 r90
  text "P0.21" at 86.818,53.171 h1.78 r90
  text "PIN" at 134.884,52.758 h1.78 r180
  text "LED 4" at 127.434,52.258 h1.91 r180
  text "(SCL)" at 20.466,52.25 h1.65 r90
  text "(SDA)" at 23.006,52.25 h1.65 r90
  text "(AREF)" at 25.546,52.25 h1.65 r90
  text "(D13)" at 30.626,52.25 h1.65 r90
  text "(D12)" at 33.166,52.249 h1.65 r90
  text "(D11)" at 35.706,52.249 h1.65 r90
  text "(D10)" at 38.246,52.25 h1.65 r90
  text "(D9)" at 40.786,52.249 h1.65 r90
  text "(D8)" at 43.326,52.249 h1.65 r90
  text "(D7)" at 47.39,52.249 h1.65 r90
  text "(D6)" at 49.93,52.249 h1.65 r90
  text "(D5)" at 52.47,52.249 h1.65 r90
  text "P0.05" at 120.704,52.256 h1.91 r180
  text "EXP" at 138.995,51.466 h1.52 r180
  text "COEX2" at 87.5,51.258 h1.27 r180
  text "P0.29" at 99.601,51.175 h1.27 r180
  text "P0.04" at 120.692,49.716 h1.91 r180
  text "LED 3" at 127.461,49.716 h1.91 r180
  text "SDATA" at 87.5,48.718 h1.27 r180
  text "SCLK" at 99.601,48.642 h1.27 r180
  text "BC" at 134.267,48.194 h1.78 r180
  text "LED 2" at 127.478,47.178 h1.91 r180
  text "P0.01" at 120.926,47.176 h1.91 r180
  text "*" at 105.134,47.117 h2.54 r180
  text "VIO" at 89.07,46.178 h1.27 r180
  text "GND" at 99.601,46.102 h1.27 r180
  text "*" at 113.643,45.212 h2.54 r180
  text "*" at 138.408,44.704 h2.54 r180
  text "LED 1" at 127.685,44.638 h1.91 r180
  text "P0.00" at 120.651,44.636 h1.91 r180
  text "VDD" at 104.964,44.377 h1.45 r180
  text "MAGPIO0" at 85.983,43.638 h1.27 r180
  text "MAGPIO1" at 99.601,43.562 h1.27 r180
  text "VDD / GPIO" at 19.765,43.208 h1.4 r90
  text "SWD / IO" at 27.416,43.013 h1.4 r90
  text "SWD / CLK" at 29.956,43.013 h1.4 r90
  text "VIN / 5V" at 40.094,43.028 h1.4 r90
  text "VDD / nRF" at 42.625,43.013 h1.4 r90
  text "VDD / 5V" at 45.165,43.013 h1.4 r90
  text "VDD" at 21.756,43.007 h1.4 r90
  text "VTG" at 24.296,43.007 h1.4 r90
  text "SWO" at 31.916,43.007 h1.4 r90
  text "RESET" at 34.456,43.006 h1.4 r90
  text "SEL" at 36.996,42.992 h1.4 r90
  text "VIO / REF" at 47.721,43.011 h1.4 r90
  text "ID" at 49.696,43.007 h1.4 r90
  text "LED" at 107.235,42.085 h2.03 r180
  text "Button" at 113.489,42.083 h2.03 r180
  text "GPIO" at 120.625,42.086 h2.03 r180
  text "Function" at 126.511,42.083 h2.03 r180
  text "Circuit" at 134.868,42.086 h2.03 r180
  text "MAGPIO2" at 86.065,41.098 h1.27 r180
  text "GND" at 99.601,41.022 h1.27 r180
  text "CTS2" at 127.906,38.799 h1.91 r180
  text "P0.17" at 120.968,38.794 h1.91 r180
  text "nRF91" at 135.496,36.991 h2.03 r180
  text "RTS2" at 128,36.259 h1.91 r180
  text "P0.16" at 120.913,36.254 h1.91 r180
  text "TxD2" at 127.878,33.716 h1.91 r180
  text "P0.29" at 120.65,33.714 h1.91 r180
  text "RESET" at 88.507,31.216 h1.91 r180
  text "RESET" at 95.517,31.216 h1.91 r180
  text "P0.21" at 102.265,31.215 h1.91 r180
  text "RxD2" at 127.866,31.176 h1.91 r180
  text "P0.28" at 120.741,31.174 h1.91 r180
  text "PIN" at 135.012,31.042 h1.78 r180
  text "nRF91" at 110.211,30.113 h2.03 r180
  text "AREF" at 88.766,28.676 h1.91 r180
  text "P0.20" at 95.711,28.676 h1.91 r180
  text "RESET" at 101.803,28.675 h1.91 r180
  text "P0.15" at 120.917,28.635 h1.91 r180
  text "CTS1" at 128.113,28.64 h1.91 r180
  text "DEF." at 108.319,28.121 h1.52 r180
  text "ALT." at 114.645,28.121 h1.52 r180
  text "BC" at 140.704,27.177 h1.78 r180
  text "D6" at 89.719,26.136 h1.91 r180
  text "P0.06" at 95.668,26.136 h1.91 r180
  text "COEX2" at 101.403,26.135 h1.91 r180
  text "PIN" at 116.561,26.134 h1.78 r180
  text "P0.14" at 120.891,26.095 h1.91 r180
  text "RTS1" at 128.207,26.1 h1.91 r180
  text "BC" at 116.561,23.884 h1.78 r180
  text "D3" at 89.743,23.596 h1.91 r180
  text "P0.03" at 95.693,23.596 h1.91 r180
  text "COEX1" at 101.61,23.595 h1.91 r180
  text "P0.27" at 120.8,23.556 h1.91 r180
  text "TxD1" at 128.085,23.557 h1.91 r180
  text "IF / MCU" at 137.53,22.74 h1.4 r180
  text "ARDUINO" at 109.877,21.22 h1.52 r180
  text "D2" at 89.76,21.056 h1.91 r180
  text "P0.02" at 95.709,21.056 h1.91 r180
  text "COEX0" at 101.342,21.055 h1.91 r180
  text "P0.26" at 120.74,21.016 h1.91 r180
  text "RxD1" at 128.073,21.017 h1.91 r180
  text "Arduino" at 87.608,18.49 h2.03 r180
  text "Default" at 94.932,18.49 h2.03 r180
  text "Alt." at 102.686,18.49 h2.03 r180
  text "Circuit" at 110.337,18.49 h2.03 r180
  text "GPIO" at 120.625,18.465 h2.03 r180
  text "Function" at 126.511,18.462 h2.03 r180
  text "Circuit" at 134.868,18.465 h2.03 r180
  text "P0.14 (A0)" at 51.2,16.522 h1.65 r90
  text "P0.18 (A4)" at 61.36,16.473 h1.65 r90
  text "P0.16 (A2)" at 56.28,16.397 h1.65 r90
  text "P0.19 (A5)" at 63.9,16.404 h1.65 r90
  text "P0.17 (A3)" at 58.82,16.308 h1.65 r90
  text "P0.15 (A1)" at 53.74,16.111 h1.65 r90
  text "P0.20" at 120.731,15.3 h1.91 r180
  text "CS" at 128.754,15.305 h1.91 r180
  text "nRF91" at 137.02,14.923 h2.03 r180
  text "RESET" at 33.518,14.062 h1.65 r90
  text "GND" at 41.138,13.338 h1.65 r90
  text "GND" at 43.678,13.338 h1.65 r90
  text "VDD" at 28.437,13.161 h1.65 r90
  text "VDD" at 30.977,13.161 h1.65 r90
  text "VDD" at 36.057,13.161 h1.65 r90
  text "N.C." at 46.256,13.023 h1.78 r90
  text "P0.13" at 120.92,12.76 h1.91 r180
  text "SCK" at 128.155,12.765 h1.91 r180
  text "J-Link" at 23.03,12.432 h1.45 r90
  text "www.segger.com" at 24.181,12.351 h1.68 r90
  text "PIN" at 134.383,12.27 h1.78 r180
  text "5V" at 38.587,11.987 h1.65 r90
  text "BC" at 142.833,11.205 h1.78 r180
  text "P0.12" at 120.931,10.22 h1.91 r180
  text "MISO" at 127.708,10.225 h1.91 r180
  text "TM" at 22.609,8.963 h0.94 r90
  text "S" at 21.171,8.749 h1.35 r90
  text "E" at 21.171,7.86 h1.35 r90
  text "EXT MEMORY" at 136.378,7.872 h1.52 r180
  text "P0.11" at 121.042,7.68 h1.91 r180
  text "MOSI" at 127.737,7.685 h1.91 r180
  text "Technology" at 23.03,7.68 h1.45 r90
  text "G" at 21.171,7.076 h1.35 r90
  text "G" at 21.171,6.085 h1.35 r90
  text "GPIO" at 120.625,5.13 h2.03 r180
  text "Function" at 126.511,5.127 h2.03 r180
  text "Circuit" at 138.424,5.13 h2.03 r180
  text "E" at 21.171,5.061 h1.35 r90
  text "R" at 21.171,4.226 h1.35 r90
Board Outline:
  lines w0.2: 148.5,13.999 148.5,0.999 cw(c147.5,0.999) 147.5,-0.001 91.9,-0.001 cw(c91.9,1.179) 91.066,0.345 ccw(c90.231,-0.49) 90.231,0.69 81.969,0.69 ccw(c81.969,-0.49) 81.134,0.345 cw(c80.3,1.179) 80.3,-0.001 1,-0.001 cw(c1,0.999) 0,0.999 0,24.12 cw(c2.716,24.12) 0.796,26.041 0.962,26.207 ; 148.5,23.099 148.5,40.399 ; 148.5,49.499 148.5,62.499 ccw(c147.5,62.499) 147.5,63.499 1,63.499 ccw(c1,62.499) 0,62.499 0,39.38 ccw(c2.716,39.38) 0.796,37.459 0.962,37.293 cw(c-0.876,35.75) 1.524,35.75 ; 0.962,26.207 ccw(c-0.876,27.75) 1.524,27.75 ; 0.962,26.207 ccw(c-0.876,27.75) 1.524,27.75 ; 1.524,27.75 1.524,35.75 ; 1.524,27.75 1.524,35.75
Top Assembly:
  drawing of 40 lines, arcs and shapes, not listed
Bottom Assembly:
  lines w0.1: 67.94,41.699 67.94,44.799 69.24,44.799 69.24,41.699 67.94,41.699 ; 70.48,41.699 70.48,44.799 71.78,44.799 71.78,41.699 70.48,41.699 ; 71.145,7.929 72.435,7.929 72.435,9.229 71.145,9.229 71.145,7.929 ; 71.145,15.299 71.145,16.599 72.435,16.599 72.435,15.299 71.145,15.299 ; 71.25,1.929 72.75,1.929 72.75,3.629 71.25,3.629 71.25,1.929 ; 71.74,16.799 71.74,18.299 73.34,18.299 73.34,16.799 71.74,16.799 ; 73.02,41.699 73.02,44.799 74.32,44.799 74.32,41.699 73.02,41.699 ; 73.55,16.629 74.35,16.629 74.35,18.309 73.55,18.309 73.55,16.629 ; 74.65,16.629 74.65,18.309 75.45,18.309 75.45,16.629 74.65,16.629 ; 75.56,41.699 75.56,44.799 76.86,44.799 76.86,41.699 75.56,41.699 ; 75.75,16.629 75.75,18.309 76.55,18.309 76.55,16.629 75.75,16.629 ; 76.85,16.629 76.85,18.309 77.65,18.309 77.65,16.629 76.85,16.629 ; 77.95,16.629 78.75,16.629 78.75,18.309 77.95,18.309 77.95,16.629 ; 78.1,41.699 79.4,41.699 79.4,44.799 78.1,44.799 78.1,41.699 ; 79.05,16.629 79.85,16.629 79.85,18.309 79.05,18.309 79.05,16.629 ; 80.15,16.629 80.15,18.309 80.95,18.309 80.95,16.629 80.15,16.629 ; 80.7,41.699 80.7,44.799 81.9,44.799 81.9,41.699 80.7,41.699 ; 81.25,16.629 82.05,16.629 82.05,18.309 81.25,18.309 81.25,16.629 ; 84.4,16.799 86,16.799 86,18.299 84.4,18.299 84.4,16.799 ; 84.75,1.929 84.75,3.629 86.25,3.629 86.25,1.929 84.75,1.929 ; 91.122,40.005 91.122,41.275 94.932,41.275 94.932,40.005 91.122,40.005 ; 91.122,42.545 94.932,42.545 94.932,43.815 91.122,43.815 91.122,42.545 ; 91.122,45.085 91.122,46.355 94.932,46.355 94.932,45.085 91.122,45.085 ; 91.122,47.625 91.122,48.895 94.932,48.895 94.932,47.625 91.122,47.625 ; 91.122,50.165 94.932,50.165 94.932,51.435 91.122,51.435 91.122,50.165 ; 91.122,52.705 91.122,53.975 94.932,53.975 94.932,52.705 91.122,52.705 ; 95.567,40.005 99.377,40.005 99.377,41.275 95.567,41.275 95.567,40.005 ; 95.567,42.545 95.567,43.815 99.377,43.815 99.377,42.545 95.567,42.545 ; 95.567,45.085 99.377,45.085 99.377,46.355 95.567,46.355 95.567,45.085 ; 95.567,47.625 99.377,47.625 99.377,48.895 95.567,48.895 95.567,47.625 ; 95.567,50.165 95.567,51.435 99.377,51.435 99.377,50.165 95.567,50.165 ; 95.567,52.705 99.377,52.705 99.377,53.975 95.567,53.975 95.567,52.705
Top Impedance Info:
  lines w0.1: 12.1,31.949 12.3,31.949 12.35,31.999 12.35,32.015 12.409,32.074 21.9,32.074 cw(c21.9,31.774) 22.2,31.774 22.2,31.299 ; 12.1,32.449 12.3,32.449 12.35,32.399 12.35,32.383 12.409,32.324 21.9,32.324 cw(c21.9,31.774) 22.45,31.774 22.45,31.299 ; 22.119,31.259 22.12,31.258 22.125,31.258 22.159,31.258 22.2,31.299 ; 22.525,31.258 22.491,31.258 22.45,31.299 ; 22.2,31.299 22.2,31.299 ; 22.45,31.299 22.45,31.299
  lines w1: 125.85,19.552 ccw(c126.703,19.552) 126.1,18.949 ccw(c127.066,19.915) 127.066,18.549 140.05,18.549 ; 130.05,21.249 133.68,21.249 ccw(c133.68,22.849) 135.28,22.849 135.28,28.849 ; 135.28,30.089 135.28,30.879 135.28,42.409 cw(c137.82,42.409) 137.82,44.949 139.85,44.949 140.1,44.949
  text "90 ohm diff impedance" at 9.69,27.773 h2
  text "50 ohm impedance, Coplanar line" at 130.85,24.075 h2 r90

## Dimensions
154,-0.001 to 90.17,55.88 on Dimensions
154,-0.001 to 66.04,40.64 on Dimensions
154,-0.001 to 66.04,12.7 on Dimensions
154,-0.001 to 96.52,7.62 on Dimensions
154,-0.001 to 147.5,63.499 on Dimensions
0,0.999 to 96.52,7.62 on Dimensions
0,0.999 to 66.04,12.7 on Dimensions
0,0.999 to 15.24,55.88 on Dimensions
0,0.999 to 13.97,7.62 on Dimensions
0,0.999 to 148.5,0.999 on Dimensions
0,0.999 to 144.829,63.5 on Dimensions
0,0.999 to 90.17,55.88 on Dimensions
147.5,0.999 to 160.7,-3.567 on Dimensions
